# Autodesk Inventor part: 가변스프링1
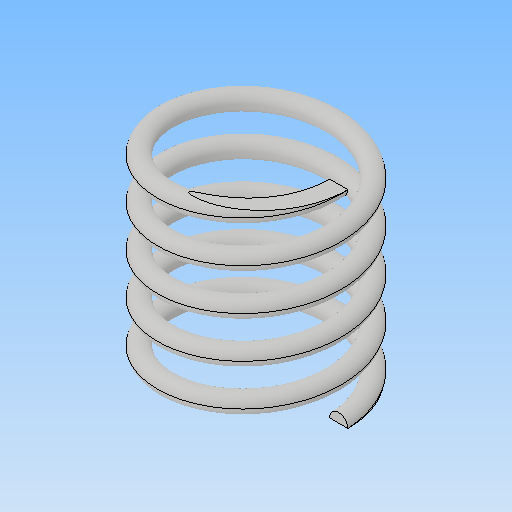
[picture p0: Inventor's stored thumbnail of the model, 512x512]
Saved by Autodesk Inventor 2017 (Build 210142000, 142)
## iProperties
Part Number: 가변스프링1
Material: 일반
Document SubType Name: Modeling
Designer: MRC
Density: 1 g/cm^3
Appearance: 기본값
Mass: 0.872289 g
Surface Area: 17.713 cm^2
Volume: 0.872289 cm^3
Author: MRC
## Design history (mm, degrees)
sketch "스케치1"
  geometry: L1 (0, 0)-(0, 22.5); L2 (0, 0)-(9, 0); L3 (0, 22.5)-(9, 22.5); C1 r 1 at (9, 0)
  constraints: 6 end point, 2 horizontal, 1 centre point, 1 coincident, 1 vertical
  dimensions: "d0" = 22.5 distance of L1.start L1.end (derived); "d1" = 9 distance of L1.start L2.end; "d2" = 9 distance of L1.end L3.end; "d3" = 2 diameter of C1
feature "코일1" sketch "스케치1" pitch "d4" = 10; turns "d6" = 5; dims "d5" = 22.5 (= d0), "d7" = 0, angle "d8" = 90 deg, angle "d9" = 90 deg, "d10" = 0, "d11" = 0
sketch "스케치2"
  geometry: L1 (22.5, 16.059)-(0, 16.059); L2 (0, 16.059)-(0, -16.059); L3 (0, -16.059)-(22.5, -16.059); L4 (22.5, -16.059)-(22.5, 16.059); 2 further points
  constraints: 8 end point, 2 parallel, 1 coincident, 1 horizontal, 1 midpoint, 1 perpendicular
  dimensions: "d12" = 22.5 distance of L2.end L3.end (= d0); "d13" = 32.11845 distance of L3.end L1.start
extrude "돌출1" sketch "스케치2" stored distance "d14" = 0; taper "d15" = 0 deg
node "솔리드1"
